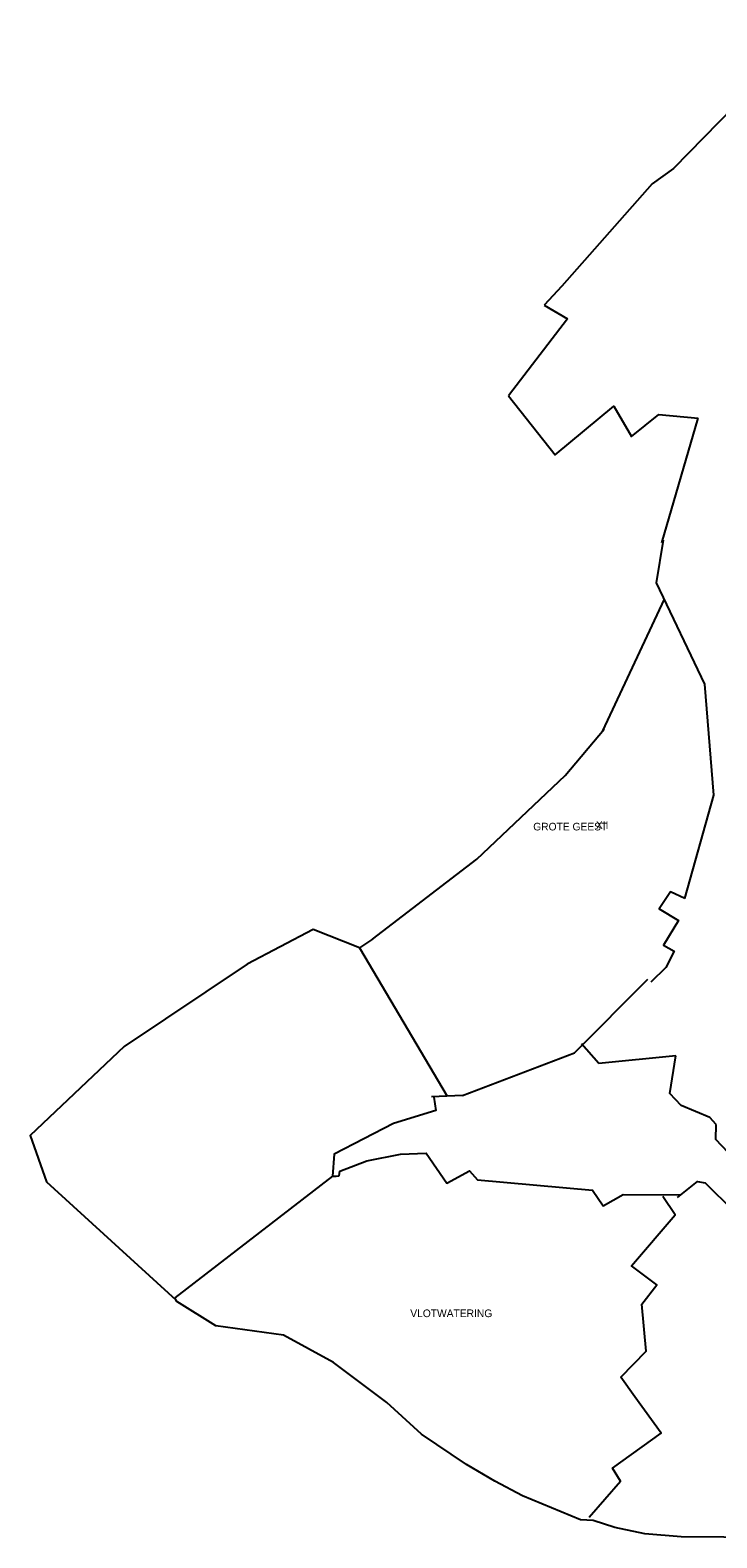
# Model space of a CAD drawing. Extents: x 69068 to 80855, y 440023 to 451362.
# Drawn here: x 70559 to 71365, y 448266 to 450037 of the extents above; entities that cross this region are included whole.
import ezdxf

# ---------------------------------------------------------------- set-up
doc = ezdxf.new("R2010")
doc.units = 0
for name, color, linetype in [('Bemalingsgebiedsgrens', 7, 'Continuous'), ('Bemalingsgebiedsnummer', 7, 'Continuous'), ('RIO_Leidingen', 7, 'Continuous')]:
    doc.layers.add(name, color=color, linetype=linetype)

msp = doc.modelspace()

# ---------------------------------------------------------------- linework, layer by layer
at = {"layer": 'Bemalingsgebiedsgrens'}
for p, q in [((71162.7, 449713.8), (71190.1, 449698)), ((71162.7, 449713.8), (71190.1, 449698)), ((71162.7, 449713.8), (71190.1, 449698)), ((71162.7, 449713.8), (71190.1, 449698)), ((71297.3, 449585.5), (71343.5, 449581.3)), ((71297.3, 449585.5), (71343.5, 449581.3)), ((71297.3, 449585.5), (71343.5, 449581.3)), ((71297.3, 449585.5), (71343.5, 449581.3)), ((71301.1, 449434.7), (71343.5, 449581.3)), ((71301.1, 449434.7), (71343.5, 449581.3)), ((71301.1, 449434.7), (71343.5, 449581.3)), ((71301.1, 449434.7), (71343.5, 449581.3)), ((71294.8, 449387.7), (71302.7, 449437.8)), ((71294.8, 449387.7), (71302.7, 449437.8)), ((71294.8, 449387.7), (71302.7, 449437.8)), ((71294.8, 449387.7), (71302.7, 449437.8)), ((71351.5, 449268.6), (71294.8, 449387.7)), ((71351.5, 449268.6), (71294.8, 449387.7)), ((71351.5, 449268.6), (71294.8, 449387.7)), ((71351.5, 449268.6), (71294.8, 449387.7)), ((71361.8, 449138.2), (71351.5, 449268.6)), ((71361.8, 449138.2), (71351.5, 449268.6)), ((71361.8, 449138.2), (71351.5, 449268.6)), ((71361.8, 449138.2), (71351.5, 449268.6)), ((71328, 449016.7), (71361.8, 449138.2)), ((71328, 449016.7), (71361.8, 449138.2)), ((71328, 449016.7), (71361.8, 449138.2)), ((71328, 449016.7), (71361.8, 449138.2)), ((71198.5, 448835.4), (71284.6, 448922)), ((71198.5, 448835.4), (71284.6, 448922)), ((71198.5, 448835.4), (71284.6, 448922)), ((71198.5, 448835.4), (71284.6, 448922)), ((71067, 448785.4), (71198.5, 448835.4)), ((71067, 448785.4), (71198.5, 448835.4)), ((71067, 448785.4), (71198.5, 448835.4)), ((71067, 448785.4), (71198.5, 448835.4)), ((71227.1, 448822.8), (71206.4, 448846.2)), ((71227.1, 448822.8), (71206.4, 448846.2)), ((71227.1, 448822.8), (71206.4, 448846.2)), ((71227.1, 448822.8), (71206.4, 448846.2)), ((71317.2, 448831.9), (71227.1, 448822.8)), ((71317.2, 448831.9), (71227.1, 448822.8)), ((71317.2, 448831.9), (71227.1, 448822.8)), ((71317.2, 448831.9), (71227.1, 448822.8)), ((71310.2, 448787.6), (71317.2, 448831.9)), ((71310.2, 448787.6), (71317.2, 448831.9)), ((71310.2, 448787.6), (71317.2, 448831.9)), ((71310.2, 448787.6), (71317.2, 448831.9)), ((71323.6, 448773.5), (71310.2, 448787.6)), ((71323.6, 448773.5), (71310.2, 448787.6)), ((71323.6, 448773.5), (71310.2, 448787.6)), ((71323.6, 448773.5), (71310.2, 448787.6)), ((71357.2, 448759.5), (71323.6, 448773.5)), ((71357.2, 448759.5), (71323.6, 448773.5)), ((71357.2, 448759.5), (71323.6, 448773.5)), ((71357.2, 448759.5), (71323.6, 448773.5)), ((71364.7, 448751.5), (71357.2, 448759.5)), ((71364.7, 448751.5), (71357.2, 448759.5)), ((71364.7, 448751.5), (71357.2, 448759.5)), ((71364.7, 448751.5), (71357.2, 448759.5)), ((71364.3, 448733.6), (71364.7, 448751.5)), ((71364.3, 448733.6), (71364.7, 448751.5)), ((71364.3, 448733.6), (71364.7, 448751.5)), ((71364.3, 448733.6), (71364.7, 448751.5)), ((71386.1, 448710.7), (71364.3, 448733.6)), ((71386.1, 448710.7), (71364.3, 448733.6)), ((71386.1, 448710.7), (71364.3, 448733.6)), ((71386.1, 448710.7), (71364.3, 448733.6)), ((70914.3, 448690.7), (70728.9, 448547.5)), ((70914.3, 448690.7), (70728.9, 448547.5)), ((70914.3, 448690.7), (70728.9, 448547.5)), ((70914.3, 448690.7), (70728.9, 448547.5))]:
    msp.add_line(p, q, dxfattribs=at)
for points in [[(71473.7, 450037), (71314.7, 449874.3), (71289.7, 449856.5), (71183.6, 449736.4), (71162.7, 449713.8)], [(71473.7, 450037), (71314.7, 449874.3), (71289.7, 449856.5), (71183.6, 449736.4), (71162.7, 449713.8)], [(71473.7, 450037), (71314.7, 449874.3), (71289.7, 449856.5), (71183.6, 449736.4), (71162.7, 449713.8)], [(71473.7, 450037), (71314.7, 449874.3), (71289.7, 449856.5), (71183.6, 449736.4), (71162.7, 449713.8)], [(71190.1, 449698), (71121, 449607.5)], [(71190.1, 449698), (71121, 449607.5)], [(71190.1, 449698), (71121, 449607.5)], [(71190.1, 449698), (71121, 449607.5)], [(71121, 449607.5), (71175.7, 449537.9), (71244.7, 449595.2), (71265.2, 449559.6), (71297.3, 449585.5)], [(71121, 449607.5), (71175.7, 449537.9), (71244.7, 449595.2), (71265.2, 449559.6), (71297.3, 449585.5)], [(71121, 449607.5), (71175.7, 449537.9), (71244.7, 449595.2), (71265.2, 449559.6), (71297.3, 449585.5)], [(71121, 449607.5), (71175.7, 449537.9), (71244.7, 449595.2), (71265.2, 449559.6), (71297.3, 449585.5)], [(71231.5, 449213.7), (71304, 449368.4)], [(71231.5, 449213.7), (71304, 449368.4)], [(71231.5, 449213.7), (71304, 449368.4)], [(71231.5, 449213.7), (71304, 449368.4)], [(70961.3, 448969.1), (71083.6, 449063.1), (71187.3, 449161.5), (71233, 449215.6)], [(70961.3, 448969.1), (71083.6, 449063.1), (71187.3, 449161.5), (71233, 449215.6)], [(70961.3, 448969.1), (71083.6, 449063.1), (71187.3, 449161.5), (71233, 449215.6)], [(70961.3, 448969.1), (71083.6, 449063.1), (71187.3, 449161.5), (71233, 449215.6)], [(71328, 449016.7), (71311, 449024.6), (71297.6, 449004.7), (71320.6, 448991.1), (71303, 448961.9), (71315.2, 448954.9), (71305.8, 448935.6), (71287.8, 448918.5)], [(71328, 449016.7), (71311, 449024.6), (71297.6, 449004.7), (71320.6, 448991.1), (71303, 448961.9), (71315.2, 448954.9), (71305.8, 448935.6), (71287.8, 448918.5)], [(71328, 449016.7), (71311, 449024.6), (71297.6, 449004.7), (71320.6, 448991.1), (71303, 448961.9), (71315.2, 448954.9), (71305.8, 448935.6), (71287.8, 448918.5)], [(71328, 449016.7), (71311, 449024.6), (71297.6, 449004.7), (71320.6, 448991.1), (71303, 448961.9), (71315.2, 448954.9), (71305.8, 448935.6), (71287.8, 448918.5)], [(70945.9, 448959), (70891.6, 448980.3), (70813.8, 448939.6), (70669.4, 448843.1), (70559.1, 448738.3), (70578.2, 448683.9), (70730.2, 448545.5)], [(70945.9, 448959), (70891.6, 448980.3), (70813.8, 448939.6), (70669.4, 448843.1), (70559.1, 448738.3), (70578.2, 448683.9), (70730.2, 448545.5)], [(70945.9, 448959), (70891.6, 448980.3), (70813.8, 448939.6), (70669.4, 448843.1), (70559.1, 448738.3), (70578.2, 448683.9), (70730.2, 448545.5)], [(70945.9, 448959), (70891.6, 448980.3), (70813.8, 448939.6), (70669.4, 448843.1), (70559.1, 448738.3), (70578.2, 448683.9), (70730.2, 448545.5)], [(70961.3, 448969.1), (70945.9, 448959), (71048.8, 448784.6)], [(70961.3, 448969.1), (70945.9, 448959), (71048.8, 448784.6)], [(70961.3, 448969.1), (70945.9, 448959), (71048.8, 448784.6)], [(70961.3, 448969.1), (70945.9, 448959), (71048.8, 448784.6)], [(71033.1, 448783.3), (71035.4, 448767.9), (70985.9, 448752.6), (70916.3, 448716.6), (70914.3, 448690.7), (70914.3, 448690.7), (70918.5, 448690.8), (70922, 448691)], [(71033.1, 448783.3), (71035.4, 448767.9), (70985.9, 448752.6), (70916.3, 448716.6), (70914.3, 448690.7), (70914.3, 448690.7), (70918.5, 448690.8), (70922, 448691)], [(71033.1, 448783.3), (71035.4, 448767.9), (70985.9, 448752.6), (70916.3, 448716.6), (70914.3, 448690.7), (70914.3, 448690.7), (70918.5, 448690.8), (70922, 448691)], [(71033.1, 448783.3), (71035.4, 448767.9), (70985.9, 448752.6), (70916.3, 448716.6), (70914.3, 448690.7), (70914.3, 448690.7), (70918.5, 448690.8), (70922, 448691)], [(71067, 448785.4), (71030.6, 448783.7)], [(71067, 448785.4), (71030.6, 448783.7)], [(71067, 448785.4), (71030.6, 448783.7)], [(71067, 448785.4), (71030.6, 448783.7)], [(70922, 448691), (70922.6, 448696.6), (70954.6, 448708.6), (70993.9, 448716.6), (71024.1, 448717.7), (71048.4, 448682.3), (71075, 448697), (71084.3, 448686.4), (71219.5, 448674), (71232.1, 448655.9), (71255.5, 448669), (71322.6, 448668.5)], [(70922, 448691), (70922.6, 448696.6), (70954.6, 448708.6), (70993.9, 448716.6), (71024.1, 448717.7), (71048.4, 448682.3), (71075, 448697), (71084.3, 448686.4), (71219.5, 448674), (71232.1, 448655.9), (71255.5, 448669), (71322.6, 448668.5)], [(70922, 448691), (70922.6, 448696.6), (70954.6, 448708.6), (70993.9, 448716.6), (71024.1, 448717.7), (71048.4, 448682.3), (71075, 448697), (71084.3, 448686.4), (71219.5, 448674), (71232.1, 448655.9), (71255.5, 448669), (71322.6, 448668.5)], [(70922, 448691), (70922.6, 448696.6), (70954.6, 448708.6), (70993.9, 448716.6), (71024.1, 448717.7), (71048.4, 448682.3), (71075, 448697), (71084.3, 448686.4), (71219.5, 448674), (71232.1, 448655.9), (71255.5, 448669), (71322.6, 448668.5)], [(71319.2, 448665.5), (71342.7, 448684.3), (71351.8, 448682.6), (71385.1, 448649.9), (71506.8, 448638.3)], [(71319.2, 448665.5), (71342.7, 448684.3), (71351.8, 448682.6), (71385.1, 448649.9), (71506.8, 448638.3)], [(71319.2, 448665.5), (71342.7, 448684.3), (71351.8, 448682.6), (71385.1, 448649.9), (71506.8, 448638.3)], [(71319.2, 448665.5), (71342.7, 448684.3), (71351.8, 448682.6), (71385.1, 448649.9), (71506.8, 448638.3)], [(71215.7, 448289.9), (71252.2, 448332.1), (71243, 448347.5), (71300.1, 448388.7), (71269.4, 448431.3), (71252.6, 448454.6), (71282.6, 448485.1), (71277.4, 448540.1), (71294.9, 448563), (71265.1, 448585.4), (71316.5, 448645), (71302.1, 448666.6)], [(71215.7, 448289.9), (71252.2, 448332.1), (71243, 448347.5), (71300.1, 448388.7), (71269.4, 448431.3), (71252.6, 448454.6), (71282.6, 448485.1), (71277.4, 448540.1), (71294.9, 448563), (71265.1, 448585.4), (71316.5, 448645), (71302.1, 448666.6)], [(71215.7, 448289.9), (71252.2, 448332.1), (71243, 448347.5), (71300.1, 448388.7), (71269.4, 448431.3), (71252.6, 448454.6), (71282.6, 448485.1), (71277.4, 448540.1), (71294.9, 448563), (71265.1, 448585.4), (71316.5, 448645), (71302.1, 448666.6)], [(71215.7, 448289.9), (71252.2, 448332.1), (71243, 448347.5), (71300.1, 448388.7), (71269.4, 448431.3), (71252.6, 448454.6), (71282.6, 448485.1), (71277.4, 448540.1), (71294.9, 448563), (71265.1, 448585.4), (71316.5, 448645), (71302.1, 448666.6)], [(71537.1, 448277.5), (71478.2, 448271.7), (71432.9, 448265.7), (71373.6, 448266.4), (71323.6, 448267), (71280.9, 448270.4), (71245.6, 448277.7), (71220.2, 448286.2), (71205.5, 448287), (71137.4, 448315), (71104.9, 448332.3), (71071.7, 448351.7), (71018.8, 448387.5), (70978, 448424.9), (70915.3, 448471.7), (70856.5, 448503.9), (70777, 448514.7), (70731.5, 448543.4), (70728.9, 448547.5)], [(71537.1, 448277.5), (71478.2, 448271.7), (71432.9, 448265.7), (71373.6, 448266.4), (71323.6, 448267), (71280.9, 448270.4), (71245.6, 448277.7), (71220.2, 448286.2), (71205.5, 448287), (71137.4, 448315), (71104.9, 448332.3), (71071.7, 448351.7), (71018.8, 448387.5), (70978, 448424.9), (70915.3, 448471.7), (70856.5, 448503.9), (70777, 448514.7), (70731.5, 448543.4), (70728.9, 448547.5)], [(71537.1, 448277.5), (71478.2, 448271.7), (71432.9, 448265.7), (71373.6, 448266.4), (71323.6, 448267), (71280.9, 448270.4), (71245.6, 448277.7), (71220.2, 448286.2), (71205.5, 448287), (71137.4, 448315), (71104.9, 448332.3), (71071.7, 448351.7), (71018.8, 448387.5), (70978, 448424.9), (70915.3, 448471.7), (70856.5, 448503.9), (70777, 448514.7), (70731.5, 448543.4), (70728.9, 448547.5)], [(71537.1, 448277.5), (71478.2, 448271.7), (71432.9, 448265.7), (71373.6, 448266.4), (71323.6, 448267), (71280.9, 448270.4), (71245.6, 448277.7), (71220.2, 448286.2), (71205.5, 448287), (71137.4, 448315), (71104.9, 448332.3), (71071.7, 448351.7), (71018.8, 448387.5), (70978, 448424.9), (70915.3, 448471.7), (70856.5, 448503.9), (70777, 448514.7), (70731.5, 448543.4), (70728.9, 448547.5)]]:
    msp.add_lwpolyline(points, dxfattribs=at)

# ---------------------------------------------------------------- texts
at = {"layer": 'Bemalingsgebiedsnummer'}
msp.add_text('XII', height=9, dxfattribs=at).set_placement((71223.5, 449098.6))
msp.add_text('XII', height=9, dxfattribs=at).set_placement((71223.5, 449098.6))
msp.add_text('XII', height=9, dxfattribs=at).set_placement((71223.5, 449098.6))
msp.add_text('XII', height=9, dxfattribs=at).set_placement((71223.5, 449098.6))
at = {"layer": 'RIO_Leidingen'}
for s, p in [('GROTE GEEST', (71149.9, 449096.8)), ('GROTE GEEST', (71149.9, 449096.8)), ('GROTE GEEST', (71149.9, 449096.8)), ('GROTE GEEST', (71149.9, 449096.8)), ('VLOTWATERING', (71005.5, 448525)), ('VLOTWATERING', (71005.5, 448525)), ('VLOTWATERING', (71005.5, 448525)), ('VLOTWATERING', (71005.5, 448525))]:
    msp.add_text(s, height=9, dxfattribs=at).set_placement(p)

doc.saveas('drawing.dxf')
